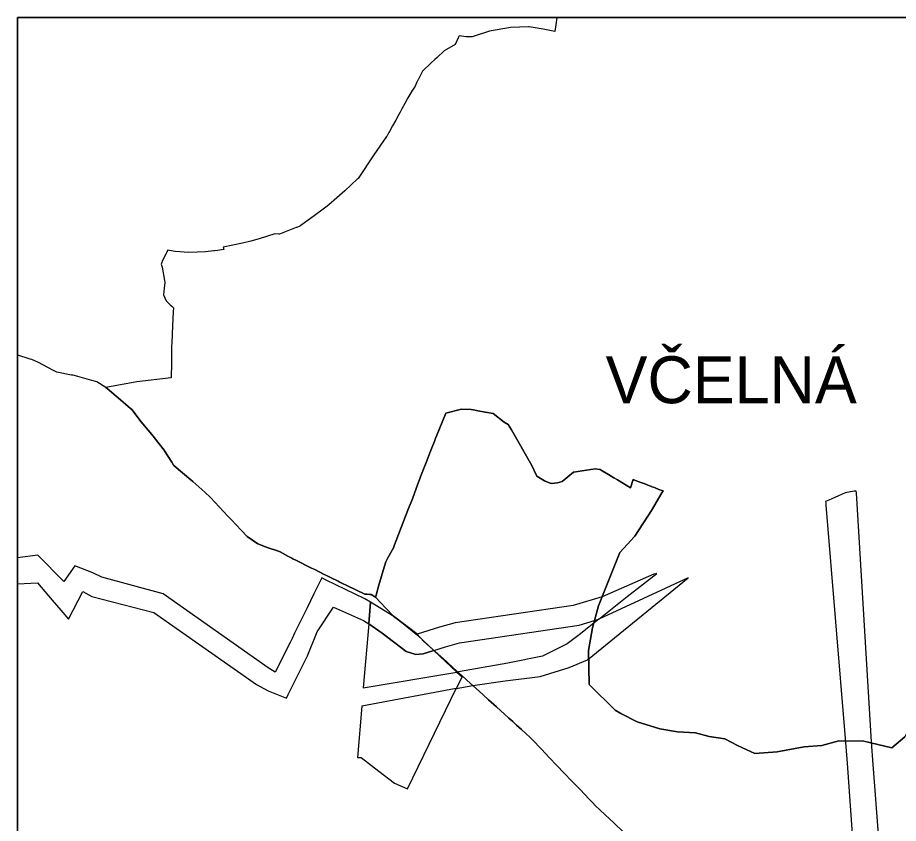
# Model space of a CAD drawing. Extents: x -759276 to -751881, y -1176141 to -1171097.
# Drawn here: x -759276 to -757130, y -1173060 to -1171097 of the extents above; entities that cross this region are included whole.
import ezdxf

# ---------------------------------------------------------------- set-up
doc = ezdxf.new("R2010")
doc.units = 0
for name, color, linetype in [('A_HRU', 7, 'Continuous'), ('A_OBCE', 7, 'Continuous'), ('A_USES', 7, 'Continuous'), ('AA_vyrezy', 7, 'Continuous')]:
    doc.layers.add(name, color=color, linetype=linetype)

msp = doc.modelspace()

# ---------------------------------------------------------------- linework, layer by layer
at = {"layer": 'A_HRU'}
for points in [[(-759275.6, -1176140.6), (-759275.6, -1171097.2), (-751880.9, -1171097.2), (-751880.9, -1176140.6)], [(-751880.9, -1172828.3), (-753894.3, -1172828.3), (-753894.3, -1171097.2), (-759275.6, -1171097.2), (-759275.6, -1176140.6), (-753894.3, -1176140.6), (-753894.3, -1174884.8), (-751880.9, -1174884.8)]]:
    msp.add_lwpolyline(points, close=True, dxfattribs=at)
at = {"layer": 'A_OBCE'}
for p, q in [((-757961.8, -1171097.2), (-757964.2, -1171114.6)), ((-756678.2, -1171097.2), (-757961.8, -1171097.2)), ((-759057.5, -1172000.3), (-759035.6, -1172019.1)), ((-759006.3, -1172044.2), (-758996.9, -1172052.3)), ((-758975.8, -1172080.8), (-758996.9, -1172052.3)), ((-758996.9, -1172052.3), (-758975.8, -1172080.8)), ((-758193.9, -1172050.9), (-758170.8, -1172051.5)), ((-758170.8, -1172051.5), (-758160.7, -1172053.5)), ((-758970.6, -1172086.9), (-758975.8, -1172080.8)), ((-758975.8, -1172080.8), (-758970.6, -1172086.9)), ((-758944.9, -1172117.2), (-758970.6, -1172086.9)), ((-758970.6, -1172086.9), (-758944.9, -1172117.2)), ((-758076.3, -1172094.8), (-758081, -1172088.5)), ((-758081, -1172088.5), (-758076.3, -1172094.8)), ((-758072.1, -1172101.5), (-758076.3, -1172094.8)), ((-758944.9, -1172117.2), (-758942.6, -1172120.2)), ((-758942.6, -1172120.2), (-758918.3, -1172150.8)), ((-758269.6, -1172153.3), (-758259.5, -1172127.4)), ((-758918.3, -1172150.8), (-758917.4, -1172152.3)), ((-758280.2, -1172180.6), (-758269.6, -1172153.3)), ((-758280.2, -1172180.6), (-758291.4, -1172209.2)), ((-758291.4, -1172209.2), (-758280.2, -1172180.6)), ((-758895.2, -1172188.4), (-758896, -1172187.2)), ((-758879, -1172201.9), (-758848.4, -1172227.2)), ((-758023, -1172188), (-758012.4, -1172211.1)), ((-757921.2, -1172204.2), (-757948.8, -1172227.2)), ((-757948.8, -1172227.2), (-757921.2, -1172204.2)), ((-757868.6, -1172196.2), (-757921.2, -1172204.2)), ((-757921.2, -1172204.2), (-757868.6, -1172196.2)), ((-757836.2, -1172210.4), (-757851.6, -1172200.8)), ((-758305, -1172243.9), (-758291.4, -1172209.2)), ((-758010.4, -1172214.1), (-758012.4, -1172211.1)), ((-757836.2, -1172210.4), (-757822.9, -1172218.4)), ((-757822.9, -1172218.4), (-757814.1, -1172223.2)), ((-757782.3, -1172242.1), (-757776.1, -1172222.3)), ((-757776.1, -1172222.3), (-757766.1, -1172226.1)), ((-758819.2, -1172252.9), (-758848.4, -1172227.2)), ((-758848.4, -1172227.2), (-758819.2, -1172252.9)), ((-758313.8, -1172268.9), (-758305, -1172243.9)), ((-757974.7, -1172231.7), (-757978.2, -1172230.8)), ((-757978.2, -1172230.8), (-757974.7, -1172231.7)), ((-757974.7, -1172231.7), (-757967.5, -1172231.3)), ((-757967.5, -1172231.3), (-757960.3, -1172230.4)), ((-757960.3, -1172230.4), (-757948.8, -1172227.2)), ((-757766.1, -1172226.1), (-757762.4, -1172227.5)), ((-757762.4, -1172227.5), (-757750.1, -1172232.1)), ((-757740.1, -1172235.9), (-757749.6, -1172232.3)), ((-757740.1, -1172235.9), (-757731.8, -1172239.2)), ((-757731.8, -1172239.2), (-757730.3, -1172239.8)), ((-757730.3, -1172239.8), (-757726.3, -1172241.2)), ((-757726.3, -1172241.2), (-757722.9, -1172242.5)), ((-757722.9, -1172242.5), (-757713.7, -1172246.7)), ((-757703.4, -1172249.6), (-757713.7, -1172246.7)), ((-757713.7, -1172246.7), (-757703.4, -1172249.6)), ((-758805.8, -1172266.1), (-758819.2, -1172252.9)), ((-758819.2, -1172252.9), (-758805.8, -1172266.1)), ((-758763.3, -1172311.4), (-758805.8, -1172266.1)), ((-758805.8, -1172266.1), (-758763.3, -1172311.4)), ((-758313.8, -1172268.9), (-758323.4, -1172292.5)), ((-758323.4, -1172292.5), (-758313.8, -1172268.9)), ((-757731.1, -1172298), (-757706.3, -1172254.8)), ((-757706.3, -1172254.8), (-757731.1, -1172298)), ((-757706.3, -1172254.8), (-757703.4, -1172249.6)), ((-757703.4, -1172249.6), (-757706.3, -1172254.8)), ((-758758.5, -1172316.5), (-758763.3, -1172311.4)), ((-758755.2, -1172320), (-758758.5, -1172316.5)), ((-758347.7, -1172356), (-758342.9, -1172343)), ((-758342.9, -1172343), (-758341.4, -1172339)), ((-758354.7, -1172374.7), (-758347.7, -1172356)), ((-758672, -1172386.6), (-758665.1, -1172388.9)), ((-758635.9, -1172398.5), (-758617.1, -1172408.6)), ((-758604.9, -1172415.1), (-758607.5, -1172413.8)), ((-758596.4, -1172419.4), (-758604.9, -1172415.1)), ((-758585.2, -1172425), (-758596.4, -1172419.4)), ((-758574, -1172430.7), (-758585.2, -1172425)), ((-758559.8, -1172437.8), (-758574, -1172430.7)), ((-758574, -1172430.7), (-758559.8, -1172437.8)), ((-758551.9, -1172441.8), (-758559.8, -1172437.8)), ((-758529.2, -1172453.2), (-758524.7, -1172455.4)), ((-758524.7, -1172455.4), (-758513.3, -1172461.1)), ((-758483.8, -1172475.6), (-758492.4, -1172471.4)), ((-758492.4, -1172471.4), (-758483.8, -1172475.6)), ((-758417.5, -1172502.1), (-758424.3, -1172501.7)), ((-758416.9, -1172502.1), (-758414, -1172502.2)), ((-758414, -1172502.2), (-758403.8, -1172508.6)), ((-758403.8, -1172508.6), (-758402.5, -1172503.8)), ((-758378.4, -1172535.4), (-758403.8, -1172508.6)), ((-758403.8, -1172508.6), (-758378.4, -1172535.4)), ((-758285.9, -1172616.6), (-758302.8, -1172598.5)), ((-758302.8, -1172598.5), (-758285.9, -1172616.6)), ((-758151.3, -1172738), (-758141.4, -1172747)), ((-758089.4, -1172794), (-758109.1, -1172776.2)), ((-758109.1, -1172776.2), (-758089.4, -1172794)), ((-758078.9, -1172803.6), (-758089.4, -1172794)), ((-758089.4, -1172794), (-758078.9, -1172803.6)), ((-757820.1, -1172784.1), (-757806.2, -1172792.5)), ((-757806.2, -1172792.5), (-757766.7, -1172812.7)), ((-757766.7, -1172812.7), (-757710.9, -1172829.4)), ((-757623.9, -1172839.6), (-757591.3, -1172848.1)), ((-757591.3, -1172848.1), (-757552.6, -1172853.7)), ((-757999.8, -1172879), (-758022.5, -1172855.3)), ((-757552.6, -1172853.7), (-757521.9, -1172870.1)), ((-757316.4, -1172869.8), (-757275.1, -1172858.4)), ((-757275.1, -1172858.4), (-757214.4, -1172859.6)), ((-757214.4, -1172859.6), (-757145.6, -1172875.4)), ((-757145.6, -1172875.4), (-757114.5, -1172849.3)), ((-757521.9, -1172870.1), (-757480, -1172889.8)), ((-757480, -1172889.8), (-757425.4, -1172885.3)), ((-757425.4, -1172885.3), (-757359.2, -1172873.1)), ((-757359.2, -1172873.1), (-757316.4, -1172869.8)), ((-757980.5, -1172899.2), (-757961.8, -1172918.7)), ((-757961.8, -1172918.7), (-757943.9, -1172937.4)), ((-757943.9, -1172937.4), (-757925.4, -1172956.7)), ((-757904.6, -1172978.5), (-757925.4, -1172956.7)), ((-757883.9, -1173000), (-757876.1, -1173008.2)), ((-757876.1, -1173008.2), (-757867.8, -1173016.9)), ((-757867.8, -1173016.9), (-757857.5, -1173026.6)), ((-757857.5, -1173026.6), (-757844.5, -1173038.8)), ((-757844.5, -1173038.8), (-757823.4, -1173058.5))]:
    msp.add_line(p, q, dxfattribs=at)
for points in [[(-757964.2, -1171114.6), (-757967, -1171131.3), (-757995.4, -1171125.2), (-758029.6, -1171119.5), (-758030.8, -1171119.5), (-758075.2, -1171121.3), (-758125.8, -1171130.2), (-758168.1, -1171143.9), (-758182.6, -1171143.8), (-758199.9, -1171141.4), (-758202.2, -1171146.5), (-758209.5, -1171162.4), (-758236.4, -1171177.7), (-758253.4, -1171194), (-758258.9, -1171199.2), (-758267.9, -1171207.7), (-758289.4, -1171228), (-758291.7, -1171232.5), (-758292.6, -1171234.3), (-758295.6, -1171240.4), (-758299.6, -1171248.3), (-758300.3, -1171249.8), (-758303.5, -1171256.3), (-758307.5, -1171264.2), (-758308.9, -1171266.8), (-758312.2, -1171271.6), (-758316.2, -1171277.4), (-758316.4, -1171277.8), (-758317.7, -1171280.1), (-758324.7, -1171292.5), (-758332.1, -1171306.1), (-758339.6, -1171319.5), (-758343.6, -1171327.2), (-758347.1, -1171333.2), (-758354.5, -1171347), (-758362, -1171360.4), (-758369.7, -1171374.5), (-758370.9, -1171376.8), (-758373.8, -1171382), (-758375.4, -1171385), (-758376.9, -1171387.1), (-758407.9, -1171431.6), (-758445.7, -1171488.8), (-758447.3, -1171490.2), (-758478.8, -1171518.7), (-758517.2, -1171553.5), (-758524.5, -1171558.8), (-758534.8, -1171566.4), (-758550.2, -1171577.6), (-758570.9, -1171592.7), (-758573.4, -1171594.6), (-758585.9, -1171603.7), (-758587.7, -1171605), (-758595.2, -1171608), (-758596.7, -1171608.6), (-758633.5, -1171623.1), (-758637.3, -1171624.6), (-758639.5, -1171624.4), (-758648.6, -1171623.7), (-758687, -1171635.6), (-758707.4, -1171641.9), (-758727.9, -1171646.3), (-758774.9, -1171656.4), (-758773.1, -1171661.7), (-758779.3, -1171662.7), (-758788.4, -1171664.2), (-758796.2, -1171665.1), (-758797.6, -1171665.3), (-758817.6, -1171667.8), (-758858.7, -1171669.4), (-758892, -1171667.2), (-758896.6, -1171666.2), (-758909.6, -1171663.2), (-758909.9, -1171664.3), (-758910.2, -1171664.2), (-758912.3, -1171668.7), (-758914.2, -1171673), (-758923.4, -1171690.1), (-758924.6, -1171693.8), (-758925.4, -1171696.4), (-758925.5, -1171697.7), (-758923.3, -1171705), (-758917.6, -1171737.7), (-758917.1, -1171742.1), (-758918.2, -1171756.1), (-758920.1, -1171772.7), (-758914.1, -1171786.9), (-758902.9, -1171797.6), (-758900.2, -1171800.1), (-758898.2, -1171801.8), (-758896.1, -1171804), (-758896.6, -1171814.1), (-758898.1, -1171847.8), (-758900.1, -1171889.4), (-758900.4, -1171897.6), (-758900.9, -1171936.5), (-758901, -1171944.6), (-758901.3, -1171968.1), (-758901.4, -1171974.9), (-758985.3, -1171984.4), (-759060.4, -1171997.9), (-759057.5, -1172000.3)], [(-759060.4, -1171997.9), (-759082.9, -1171984.6), (-759094.7, -1171981.1), (-759140.6, -1171968.1), (-759144.4, -1171968.1), (-759180.2, -1171960.4), (-759189.7, -1171955.6), (-759224.4, -1171937.1), (-759240.6, -1171930.1), (-759245, -1171928.9), (-759275.4, -1171919.1), (-759275.6, -1171919)], [(-759275.6, -1171919), (-759275.6, -1176140.6), (-756918.3, -1176140.6)], [(-758996.9, -1172052.3), (-759006.3, -1172044.2), (-759025.3, -1172027.9), (-759035.6, -1172019.1), (-759057.5, -1172000.3), (-759060.4, -1171997.9)], [(-759035.6, -1172019.1), (-759025.3, -1172027.9), (-759006.3, -1172044.2)], [(-758193.9, -1172050.9), (-758232.1, -1172060.4), (-758248.8, -1172100.4), (-758258.5, -1172123.7), (-758259.5, -1172127.4)], [(-758259.5, -1172127.4), (-758258.5, -1172123.7), (-758248.8, -1172100.4), (-758232.1, -1172060.4), (-758193.9, -1172050.9)], [(-758160.7, -1172053.5), (-758170.8, -1172051.5), (-758193.9, -1172050.9)], [(-758081, -1172088.5), (-758090.2, -1172082.6), (-758117.4, -1172061.7), (-758154.6, -1172054.6), (-758160.7, -1172053.5)], [(-758160.7, -1172053.5), (-758154.6, -1172054.6), (-758117.4, -1172061.7), (-758090.2, -1172082.6), (-758081, -1172088.5)], [(-758076.3, -1172094.8), (-758072.1, -1172101.5), (-758023, -1172188)], [(-758917.4, -1172152.3), (-758918.3, -1172150.8), (-758942.6, -1172120.2), (-758944.9, -1172117.2)], [(-758012.4, -1172211.1), (-758023, -1172188), (-758072.1, -1172101.5)], [(-758259.5, -1172127.4), (-758269.6, -1172153.3), (-758280.2, -1172180.6)], [(-758896, -1172187.2), (-758900.3, -1172180.1), (-758917.4, -1172152.3)], [(-758917.4, -1172152.3), (-758900.3, -1172180.1), (-758896, -1172187.2), (-758895.2, -1172188.4), (-758879, -1172201.9)], [(-758848.4, -1172227.2), (-758879, -1172201.9), (-758895.2, -1172188.4)], [(-757851.6, -1172200.8), (-757856.5, -1172197.8), (-757868.6, -1172196.2)], [(-757868.6, -1172196.2), (-757856.5, -1172197.8), (-757851.6, -1172200.8), (-757836.2, -1172210.4)], [(-758291.4, -1172209.2), (-758305, -1172243.9), (-758313.8, -1172268.9)], [(-758012.4, -1172211.1), (-758010.4, -1172214.1), (-757992.4, -1172225.8), (-757978.2, -1172230.8)], [(-757978.2, -1172230.8), (-757992.4, -1172225.8), (-758010.4, -1172214.1)], [(-757792.9, -1172235.9), (-757814.1, -1172223.2), (-757822.9, -1172218.4), (-757836.2, -1172210.4)], [(-757814.1, -1172223.2), (-757792.9, -1172235.9), (-757782.3, -1172242.1)], [(-757776.1, -1172222.3), (-757782.3, -1172242.1), (-757792.9, -1172235.9)], [(-757749.6, -1172232.3), (-757750.1, -1172232.1), (-757762.4, -1172227.5), (-757766.1, -1172226.1), (-757776.1, -1172222.3)], [(-757948.8, -1172227.2), (-757960.3, -1172230.4), (-757967.5, -1172231.3), (-757974.7, -1172231.7)], [(-757750.1, -1172232.1), (-757749.6, -1172232.3), (-757740.1, -1172235.9)], [(-757726.3, -1172241.2), (-757730.3, -1172239.8), (-757731.8, -1172239.2), (-757740.1, -1172235.9)], [(-757713.7, -1172246.7), (-757722.9, -1172242.5), (-757726.3, -1172241.2)], [(-758763.3, -1172311.4), (-758758.5, -1172316.5), (-758755.2, -1172320), (-758730.9, -1172345.9), (-758716.3, -1172361.4)], [(-758323.4, -1172292.5), (-758331.1, -1172311.4), (-758341.4, -1172339)], [(-758341.4, -1172339), (-758331.1, -1172311.4), (-758323.4, -1172292.5)], [(-757885, -1172639.1), (-757874.8, -1172583.6), (-757860.9, -1172529.9), (-757808.7, -1172400.4), (-757772.1, -1172360.3), (-757731.1, -1172298)], [(-757731.1, -1172298), (-757772.1, -1172360.3), (-757808.7, -1172400.4), (-757860.9, -1172529.9), (-757874.8, -1172583.6), (-757885, -1172639.1), (-757883.5, -1172721.4), (-757820.1, -1172784.1)], [(-758635.9, -1172398.5), (-758642.9, -1172396.2), (-758665.1, -1172388.9), (-758672, -1172386.6), (-758690.5, -1172378.9), (-758716.3, -1172361.4), (-758730.9, -1172345.9), (-758755.2, -1172320)], [(-758341.4, -1172339), (-758342.9, -1172343), (-758347.7, -1172356), (-758354.7, -1172374.7), (-758358.1, -1172383.6), (-758360, -1172388.7)], [(-758716.3, -1172361.4), (-758690.5, -1172378.9), (-758672, -1172386.6)], [(-758360, -1172388.7), (-758358.1, -1172383.6), (-758354.7, -1172374.7)], [(-758665.1, -1172388.9), (-758642.9, -1172396.2), (-758635.9, -1172398.5)], [(-758360, -1172388.7), (-758373.4, -1172413), (-758378.7, -1172422.6), (-758385.1, -1172443.9), (-758393.4, -1172471.1), (-758394.8, -1172476.3)], [(-758378.7, -1172422.6), (-758373.4, -1172413), (-758360, -1172388.7)], [(-758607.5, -1172413.8), (-758617.1, -1172408.6), (-758635.9, -1172398.5)], [(-758617.1, -1172408.6), (-758607.5, -1172413.8), (-758604.9, -1172415.1), (-758596.4, -1172419.4), (-758585.2, -1172425), (-758574, -1172430.7)], [(-758559.8, -1172437.8), (-758551.9, -1172441.8), (-758529.2, -1172453.2)], [(-758402.5, -1172503.8), (-758394.8, -1172476.3), (-758393.4, -1172471.1), (-758385.1, -1172443.9), (-758378.7, -1172422.6)], [(-758492.4, -1172471.4), (-758495, -1172470.1), (-758513.3, -1172461.1), (-758524.7, -1172455.4), (-758529.2, -1172453.2), (-758551.9, -1172441.8)], [(-758513.3, -1172461.1), (-758495, -1172470.1), (-758492.4, -1172471.4)], [(-758429.8, -1172501.5), (-758473.5, -1172480.5), (-758483.8, -1172475.6)], [(-758483.8, -1172475.6), (-758473.5, -1172480.5), (-758429.8, -1172501.5), (-758426.5, -1172501.7), (-758424.3, -1172501.7)], [(-758394.8, -1172476.3), (-758402.5, -1172503.8), (-758403.8, -1172508.6)], [(-758424.3, -1172501.7), (-758426.5, -1172501.7), (-758429.8, -1172501.5)], [(-758424.3, -1172501.7), (-758417.5, -1172502.1), (-758416.9, -1172502.1)], [(-758403.8, -1172508.6), (-758414, -1172502.2), (-758416.9, -1172502.1), (-758417.5, -1172502.1)], [(-758302.8, -1172598.5), (-758360, -1172554.8), (-758378.4, -1172535.4)], [(-758378.4, -1172535.4), (-758360, -1172554.8), (-758302.8, -1172598.5)], [(-758192.7, -1172700.5), (-758213.4, -1172681.7), (-758231, -1172665.8), (-758285.9, -1172616.6)], [(-758285.9, -1172616.6), (-758231, -1172665.8), (-758213.4, -1172681.7)], [(-757820.1, -1172784.1), (-757883.5, -1172721.4), (-757885, -1172639.1)], [(-758213.4, -1172681.7), (-758192.7, -1172700.5), (-758172.6, -1172718.7), (-758151.3, -1172738)], [(-758141.4, -1172747), (-758151.3, -1172738), (-758172.6, -1172718.7), (-758192.7, -1172700.5)], [(-758109.1, -1172776.2), (-758128.5, -1172758.7), (-758141.4, -1172747)], [(-758141.4, -1172747), (-758128.5, -1172758.7), (-758109.1, -1172776.2)], [(-758060.1, -1172820.7), (-758069.6, -1172812), (-758078.9, -1172803.6)], [(-758078.9, -1172803.6), (-758069.6, -1172812), (-758060.1, -1172820.7)], [(-757623.9, -1172839.6), (-757668.3, -1172837.1), (-757710.9, -1172829.4), (-757766.7, -1172812.7), (-757806.2, -1172792.5), (-757820.1, -1172784.1)], [(-757093, -1172797.4), (-757110.2, -1172840.8), (-757114.5, -1172849.3), (-757145.6, -1172875.4)], [(-758022.5, -1172855.3), (-758026.7, -1172850.9), (-758048.3, -1172831.4), (-758060.1, -1172820.7)], [(-758060.1, -1172820.7), (-758048.3, -1172831.4), (-758026.7, -1172850.9), (-758022.5, -1172855.3)], [(-757710.9, -1172829.4), (-757668.3, -1172837.1), (-757623.9, -1172839.6)], [(-757521.9, -1172870.1), (-757552.6, -1172853.7), (-757591.3, -1172848.1), (-757623.9, -1172839.6)], [(-758022.5, -1172855.3), (-757999.8, -1172879), (-757980.5, -1172899.2)], [(-757145.6, -1172875.4), (-757214.4, -1172859.6), (-757275.1, -1172858.4), (-757316.4, -1172869.8), (-757359.2, -1172873.1)], [(-757961.8, -1172918.7), (-757980.5, -1172899.2), (-757999.8, -1172879)], [(-757359.2, -1172873.1), (-757425.4, -1172885.3), (-757480, -1172889.8), (-757521.9, -1172870.1)], [(-757925.4, -1172956.7), (-757943.9, -1172937.4), (-757961.8, -1172918.7)], [(-757925.4, -1172956.7), (-757904.6, -1172978.5), (-757883.9, -1173000)], [(-757876.1, -1173008.2), (-757883.9, -1173000), (-757904.6, -1172978.5)], [(-757857.5, -1173026.6), (-757867.8, -1173016.9), (-757876.1, -1173008.2)], [(-757823.4, -1173058.5), (-757844.5, -1173038.8), (-757857.5, -1173026.6)], [(-757747.8, -1173129.5), (-757759.2, -1173118.9), (-757779.4, -1173099.9), (-757799.3, -1173081.2), (-757823.4, -1173058.5)], [(-757823.4, -1173058.5), (-757799.3, -1173081.2), (-757779.4, -1173099.9)]]:
    msp.add_lwpolyline(points, dxfattribs=at)
at = {"layer": 'A_USES'}
for p, q in [((-757307.3, -1172275.4), (-757307, -1172278.9)), ((-757642.5, -1172461.4), (-757860.1, -1172562.4)), ((-758415.9, -1172521), (-758420.4, -1172574)), ((-758420.4, -1172574), (-758415.9, -1172521)), ((-758359, -1172555.8), (-758415.9, -1172521)), ((-758339.7, -1172570.4), (-758359, -1172555.8)), ((-758420.4, -1172574), (-758433.6, -1172729.6)), ((-758339.7, -1172570.4), (-758331.6, -1172577.4)), ((-758331.6, -1172577.4), (-758339.7, -1172570.4)), ((-758205.6, -1172691.2), (-758261.7, -1172638.7)), ((-758433.6, -1172729.6), (-758205.6, -1172691.2)), ((-758205.6, -1172691.2), (-758193, -1172703)), ((-758193, -1172703), (-758206.9, -1172731.6)), ((-758206.9, -1172731.6), (-758437.4, -1172774)), ((-758437.4, -1172774), (-758448, -1172899.3))]:
    msp.add_line(p, q, dxfattribs=at)
for points in [[(-757232.6, -1172250.7), (-757238.1, -1172250.9), (-757259.7, -1172255), (-757285, -1172266.2), (-757299.7, -1172272.3), (-757307.3, -1172275.4)], [(-757191.6, -1172916.7), (-757195.5, -1172861.3), (-757232.3, -1172254.9), (-757232.6, -1172250.7)], [(-757307, -1172278.9), (-757306.9, -1172279.5), (-757306.5, -1172284.8)], [(-757306.5, -1172284.8), (-757259.7, -1172853.3), (-757254.8, -1172912.9)], [(-758415.9, -1172521), (-758429.7, -1172512.6), (-758523.9, -1172467), (-758534.7, -1172461.7), (-758554, -1172501), (-758570.6, -1172534.8), (-758601, -1172596.7), (-758607, -1172609.4), (-758611.8, -1172619.6), (-758648.3, -1172691.4), (-758664.9, -1172681), (-758921.2, -1172500.8), (-759070.8, -1172460.3), (-759092.3, -1172449.6), (-759135.9, -1172432.6), (-759162.9, -1172470.7), (-759226.4, -1172406.2), (-759275.6, -1172413)], [(-757718.7, -1172451.5), (-757725.6, -1172452.7), (-757852, -1172507.9), (-757922.6, -1172529.5), (-758209.9, -1172571.1), (-758247.5, -1172582.1), (-758302.2, -1172598.7), (-758339.7, -1172570.4)], [(-758206.9, -1172731.6), (-758166.3, -1172724.1), (-758087.6, -1172712.9), (-758002.3, -1172702.1), (-757932.1, -1172680.5), (-757887.2, -1172661.1), (-757642.5, -1172461.4)], [(-757860.1, -1172562.4), (-757790.8, -1172507), (-757718.7, -1172451.5)], [(-757718.7, -1172451.5), (-757718.7, -1172451.5)], [(-759275.6, -1172476), (-759227.3, -1172473.9), (-759191.1, -1172516.3), (-759170.6, -1172540.5), (-759152, -1172562), (-759117.1, -1172494.8), (-759094.6, -1172507.1), (-758943.7, -1172546.1), (-758693.7, -1172721.9), (-758665.6, -1172737.3), (-758620.2, -1172754.5), (-758616.2, -1172746.1), (-758569.7, -1172652.1), (-758546.2, -1172593.6), (-758506.2, -1172532.9), (-758433, -1172565.3), (-758420.4, -1172574)], [(-758261.7, -1172638.7), (-758233.2, -1172630), (-758199.2, -1172620.1), (-757908, -1172577.3), (-757860.1, -1172562.4), (-757860.1, -1172562.4)], [(-757860.1, -1172562.4), (-757860.1, -1172562.4), (-757868.2, -1172568.9), (-757907.8, -1172600.6), (-757936.5, -1172622.2), (-757996.9, -1172652.4), (-758081.1, -1172669.7), (-758201.5, -1172690.5), (-758205.6, -1172691.2)], [(-758261.7, -1172638.7), (-758287.6, -1172646.6), (-758305.3, -1172648.6), (-758329, -1172641), (-758387.5, -1172596.9), (-758420.4, -1172574)], [(-758420.4, -1172574), (-758387.5, -1172596.9), (-758329, -1172641)], [(-758331.6, -1172577.4), (-758301.3, -1172601.5), (-758261.7, -1172638.7)], [(-758261.7, -1172638.7), (-758301.3, -1172601.5), (-758331.6, -1172577.4)], [(-758329, -1172641), (-758305.3, -1172648.6), (-758287.6, -1172646.6), (-758261.7, -1172638.7)], [(-758448, -1172899.3), (-758438.7, -1172899.3), (-758396, -1172932.7), (-758357.6, -1172961.8), (-758326.1, -1172976), (-758206.9, -1172731.6)], [(-757254.8, -1172912.9), (-757240.4, -1173120.3), (-757191.3, -1173099.9), (-757177.4, -1173096.9), (-757191.6, -1172916.7)]]:
    msp.add_lwpolyline(points, dxfattribs=at)

# ---------------------------------------------------------------- texts
at = {"layer": 'AA_vyrezy'}
msp.add_text('VČELNÁ', height=114.37, dxfattribs=at).set_placement((-757843.3, -1172036.5))

doc.saveas('drawing.dxf')
